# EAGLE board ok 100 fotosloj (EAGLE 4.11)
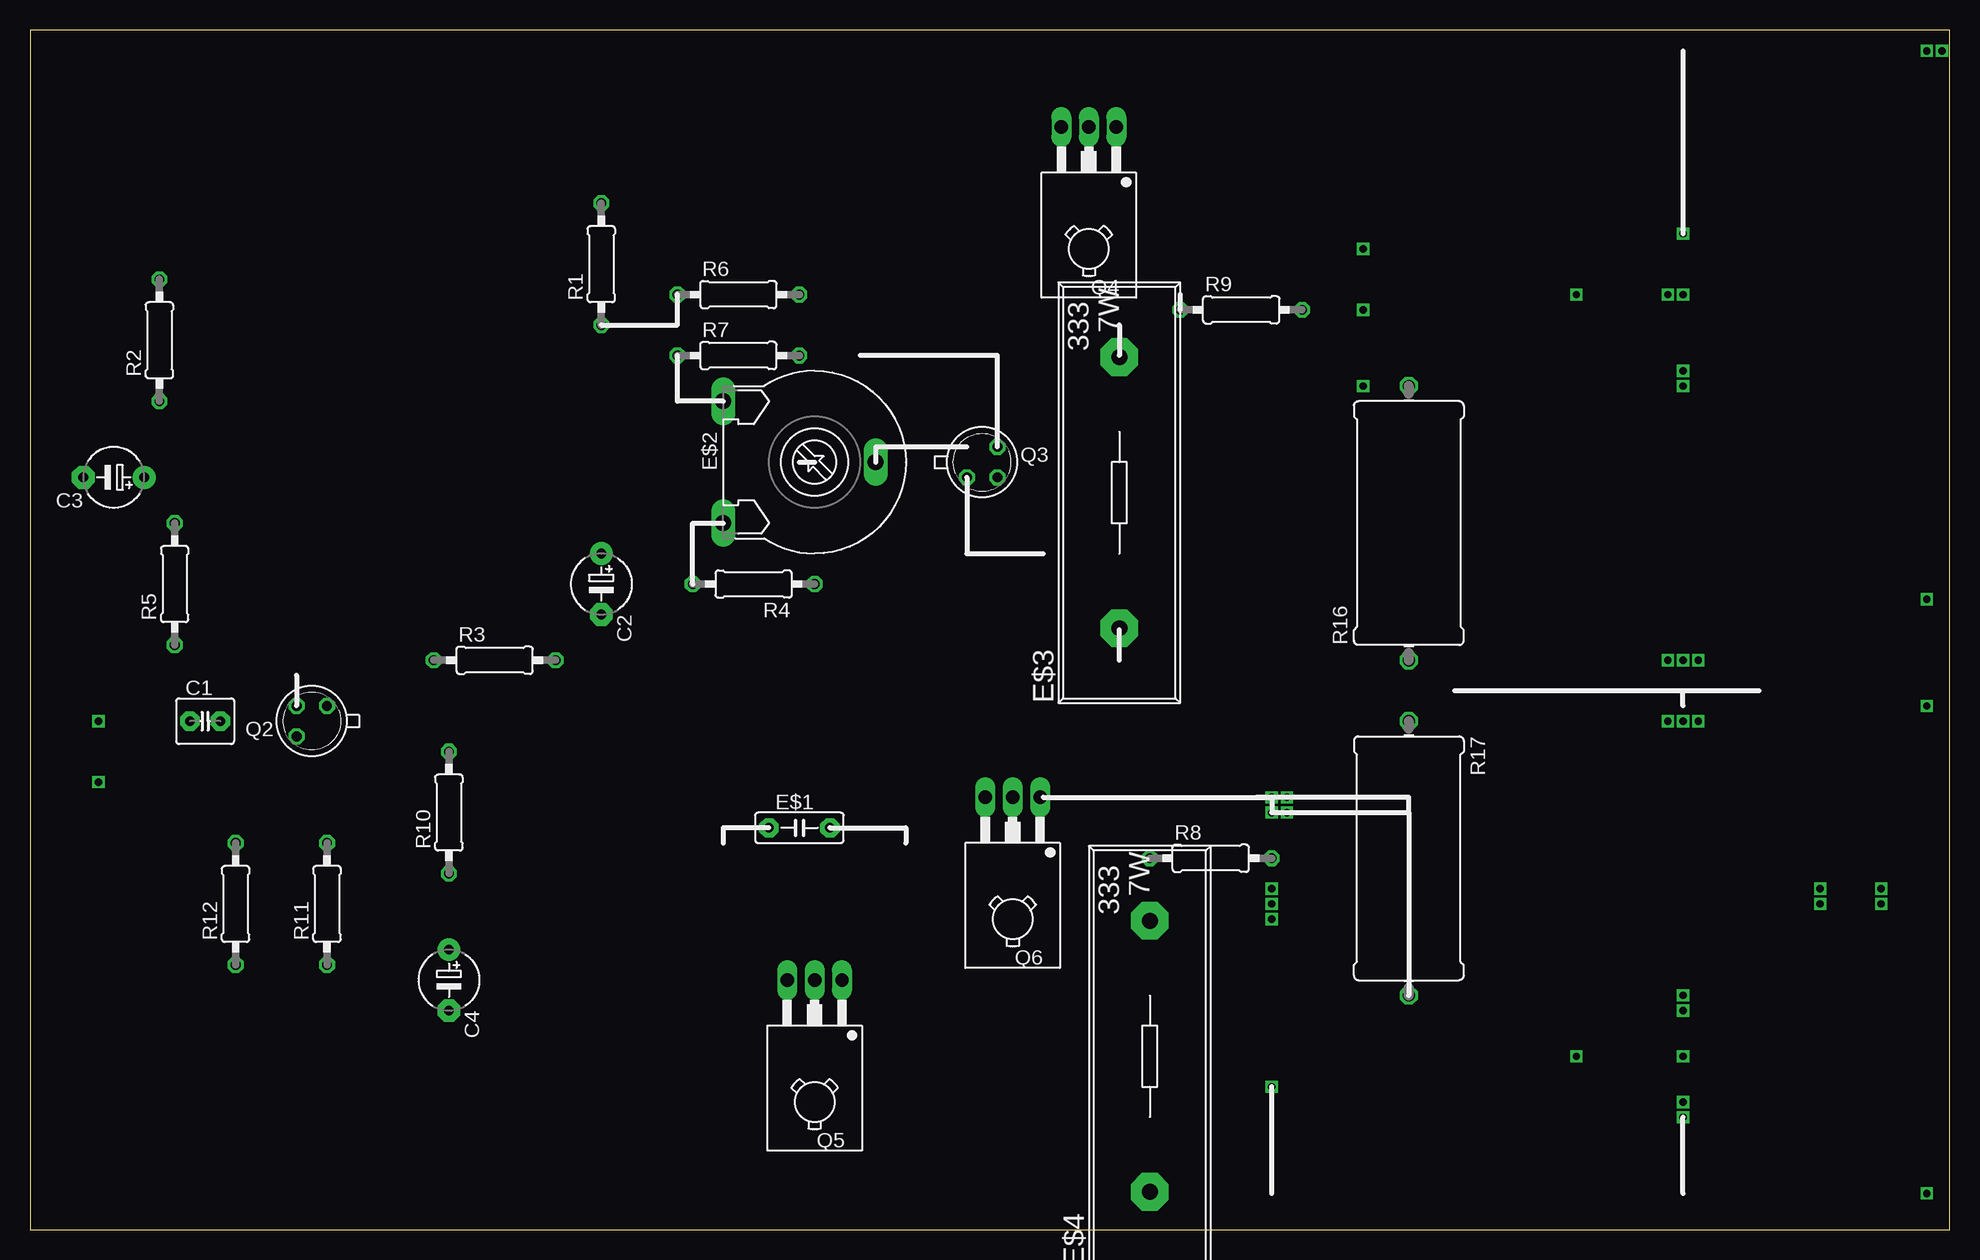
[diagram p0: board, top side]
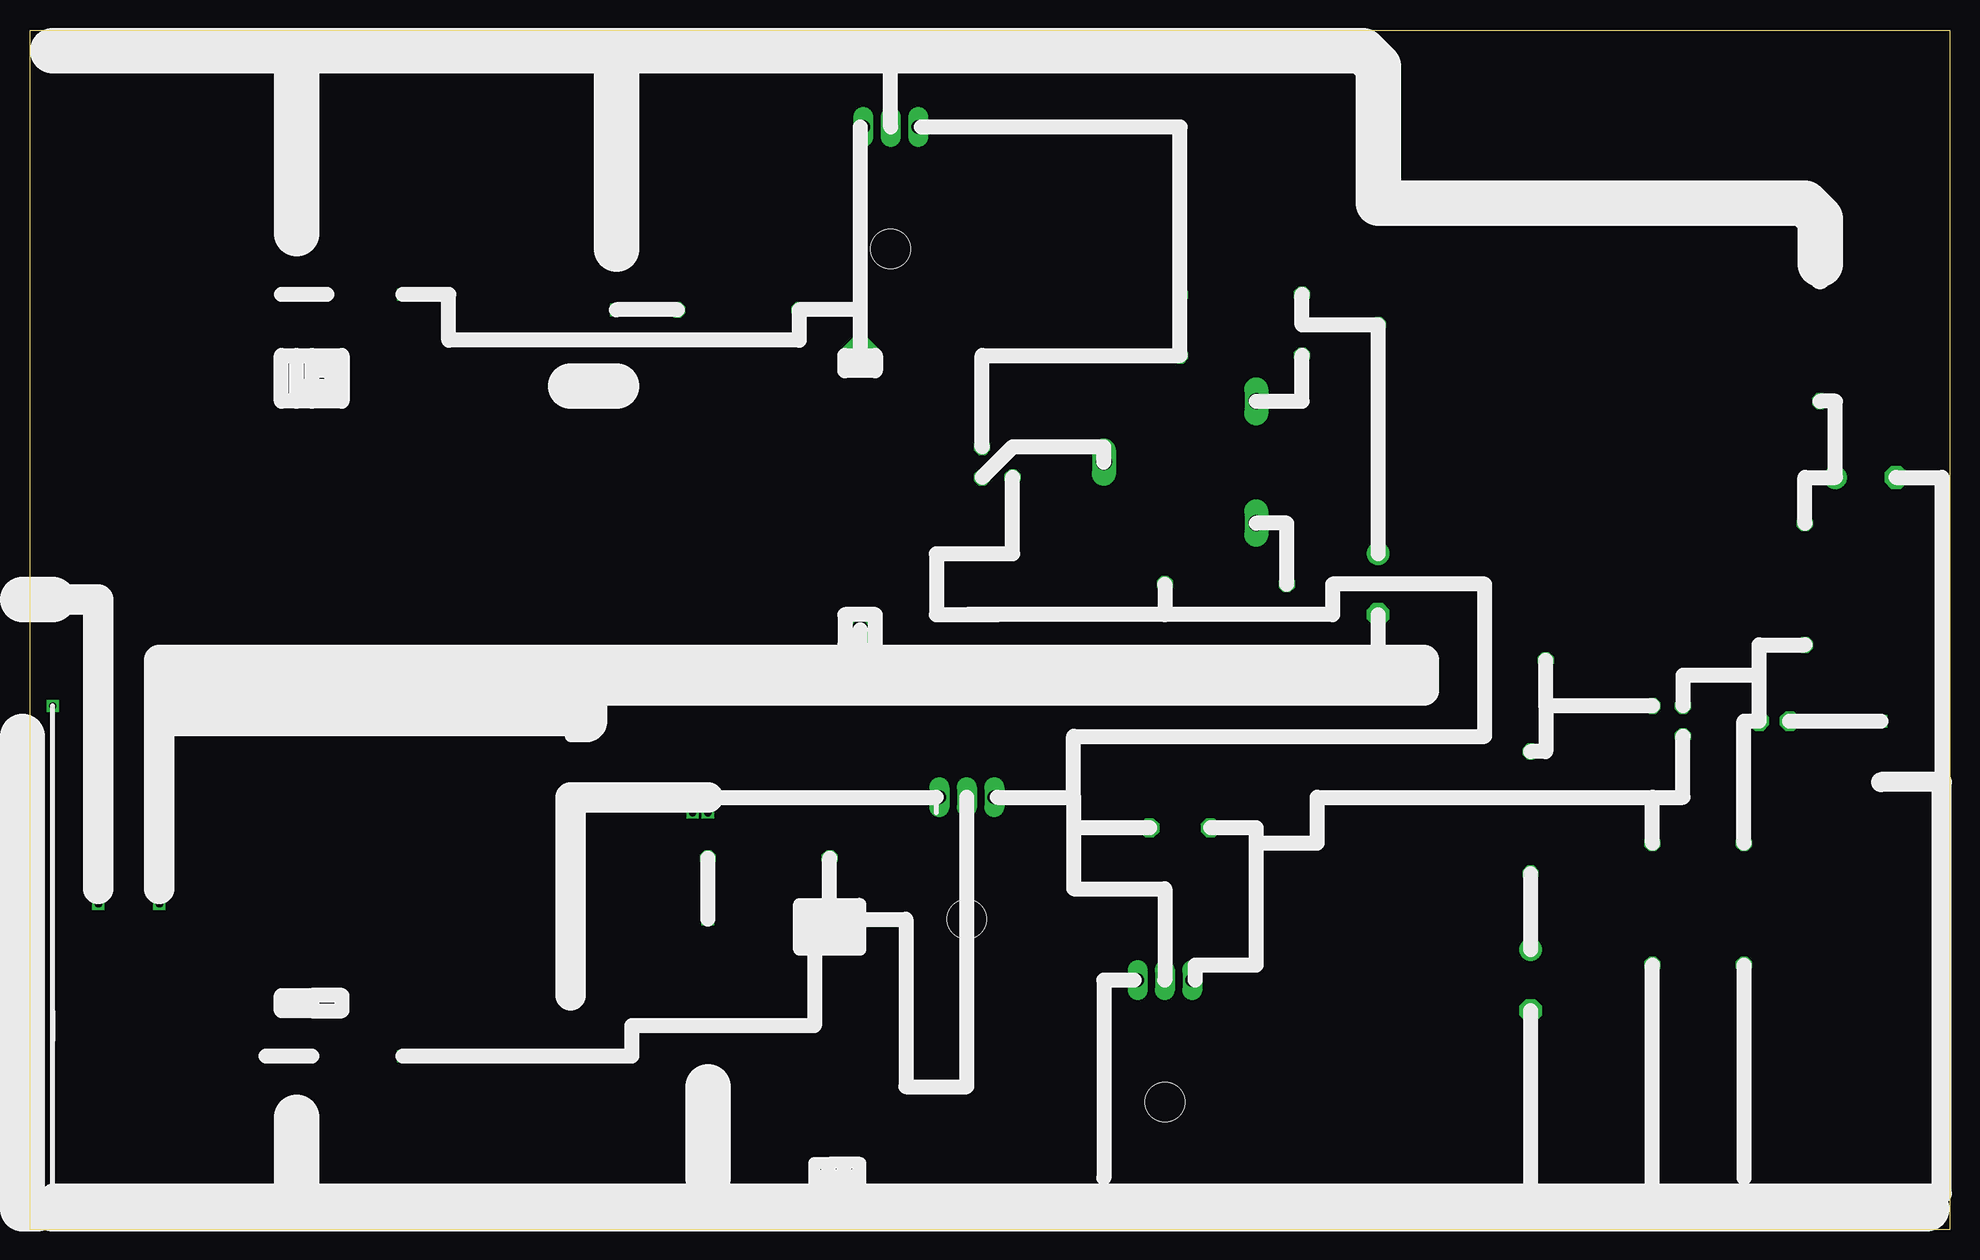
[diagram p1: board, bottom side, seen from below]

Size 160 x 100 mm. Coordinates in mm from the lower left corner, seen from the top.
Outline: 0,0 160,0 160,100 0,100 0,0
Copper layers (1*16): Top 0.035mm / dielectric 1.5mm / Bottom 0.035mm
Design rules "default": minimum track width 10mil, minimum drill 24mil, track to track 8mil, track to pad 8mil, pad to pad 8mil, via to via 8mil, smd to smd 8mil, copper to edge 40mil, drill to drill 8mil, minimum pad ring 10mil, minimum via ring 8mil, stop-mask expansion 4mil, vias tented up to drill 0mil, thermal gap 10mil
bKeepout: 1 lines

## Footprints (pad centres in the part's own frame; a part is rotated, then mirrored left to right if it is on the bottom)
C2.5-4 = drill 0.813 pad 1.6 octagon: 1 -1.27,0; 2 1.27,0
E5-5 = drill 0.813 pad 1.905 round: + -2.54,0 | drill 0.813 pad 1.905 octagon: - 2.54,0
C5B2.5 = drill 0.813 pad 1.6 octagon: 1 -2.54,0; 2 2.54,0
LI15 = drill 1.321 long: A -5.08,-7.62; E 5.08,-7.62; S 0,5.08
KWP333 = drill 1.321 pad 3.15 octagon: 1 -11.303,0; 2 11.303,0
TO18 = drill 0.813 octagon: 1 -1.27,-1.27; 2 1.27,-1.27; 3 1.27,1.27
TO126 = drill 1.118 long: 1 -2.286,-5.08; 2 0,-5.08; 3 2.286,-5.08 | hole 3.302: 0,5.08
0207/10 = drill 0.813 octagon: 1 -5.08,0; 2 5.08,0
0922/22 = drill 1.016 octagon: 1 -11.43,0; 2 11.43,0

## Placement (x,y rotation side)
C1  [C2.5-4]  14.6,42.38 0 top
C2  [E5-5]  47.62,53.81 270 top
C3  [E5-5]  6.98,62.7 180 top
C4  [E5-5]  34.92,20.79 270 top
E$1  [C5B2.5]  64.13,33.49 0 top
E$2  [LI15]  65.4,63.97 270 top
E$3  [KWP333]  90.8,61.43 90 top
E$4  [KWP333]  93.34,14.44 90 top
Q2  BC177  [TO18]  23.49,42.38 180 top
Q3  BC107  [TO18]  79.37,63.97 0 top
Q4  BD441  [TO126]  88.26,86.83 180 top
Q5  BD441  [TO126]  65.4,15.71 180 top
Q6  BD442  [TO126]  81.91,30.95 180 top
R1  [0207/10]  47.62,80.48 90 top
R2  [0207/10]  10.79,74.13 90 top
R3  [0207/10]  38.73,47.46 0 top
R4  [0207/10]  60.32,53.81 180 top
R5  [0207/10]  12.06,53.81 90 top
R6  [0207/10]  59.05,77.94 0 top
R7  [0207/10]  59.05,72.86 0 top
R8  [0207/10]  98.42,30.95 0 top
R9  [0207/10]  100.96,76.67 0 top
R10  [0207/10]  34.92,34.76 90 top
R11  [0207/10]  24.76,27.14 90 top
R12  [0207/10]  17.14,27.14 90 top
R16  [0922/22]  114.93,58.89 90 top
R17  [0922/22]  114.93,30.95 270 top

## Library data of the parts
C1 E$1 = capacitor-wima
C2-C4 R1-R12 R16 R17 = rcl
E$2 = pot
E$3 E$4 = resistor-power
Q2 Q6 = transistor-pnp
Q3-Q5 = transistor-npn

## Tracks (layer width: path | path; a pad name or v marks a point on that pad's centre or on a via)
N$1  (via drill 0.61)
  other vias: 103.5,28.41
N$2  (via drill 0.61)
  other vias: 103.5,34.76
N$4  (via drill 0.61)
  other vias: 158.11,43.65
N$5  (via drill 0.61)
  other vias: 158.11,52.54
N$6  (via drill 0.61)
  other vias: 111.12,76.67
N$7  (via drill 0.61)
  other vias: 111.12,70.32
N$8  (via drill 0.61)
  other vias: 111.12,81.75
N$9  (via drill 0.61)
  other vias: 5.71,37.3
N$10  (via drill 0.61)
  other vias: 158.11,98.26
N$11  (via drill 0.61)
  other vias: 158.11,3.01
N$12  (via drill 0.61)
  other vias: 159.38,98.26
N$13  (via drill 0.61)
  other vias: 5.71,42.38
S$1  (via drill 0.61)
  other vias: 128.9,14.44
S$2  (via drill 0.61)
  other vias: 136.52,77.94
S$3
  Bottom 0.406: 90.8,50 90.8,47.46
S$4
  Bottom 0.406: 90.8,75.4 90.8,72.86
S$5  (via drill 0.61)
  other vias: 137.79,77.94
S$6  (via drill 0.61)
  other vias: 137.79,83.02
S$7  (via drill 0.61)
  other vias: 137.79,47.46
S$8  (via drill 0.61)
  other vias: 139.06,47.46
S$9  (via drill 0.61)
  other vias: 136.52,47.46
S$10  (via drill 0.61)
  other vias: 137.79,70.32
S$11  (via drill 0.61)
  other vias: 137.79,71.59
S$12  (via drill 0.61)
  other vias: 137.79,42.38
S$13  (via drill 0.61)
  other vias: 139.06,42.38
S$14  (via drill 0.61)
  other vias: 136.52,42.38
S$15  (via drill 0.61)
  other vias: 137.79,19.52
S$16  (via drill 0.61)
  other vias: 137.79,18.25
S$17  (via drill 0.61)
  other vias: 137.79,14.44
S$18  (via drill 0.61)
  other vias: 103.5,11.9
S$19  (via drill 0.61)
  other vias: 103.5,36.03
S$20  (via drill 0.61)
  other vias: 104.77,36.03
S$21  (via drill 0.61)
  other vias: 104.77,34.76
S$22  (via drill 0.61)
  other vias: 103.5,27.14
S$23  (via drill 0.61)
  other vias: 103.5,25.87
S$24  (via drill 0.61)
  other vias: 149.22,27.14
S$25  (via drill 0.61)
  other vias: 154.3,27.14
S$26  (via drill 0.61)
  other vias: 137.79,9.36
S$27  (via drill 0.61)
  other vias: 137.79,10.63
S$28  (via drill 0.61)
  other vias: 149.22,28.41
S$29  (via drill 0.61)
  other vias: 154.3,28.41
S$30  (via drill 0.61)
  other vias: 128.9,77.94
